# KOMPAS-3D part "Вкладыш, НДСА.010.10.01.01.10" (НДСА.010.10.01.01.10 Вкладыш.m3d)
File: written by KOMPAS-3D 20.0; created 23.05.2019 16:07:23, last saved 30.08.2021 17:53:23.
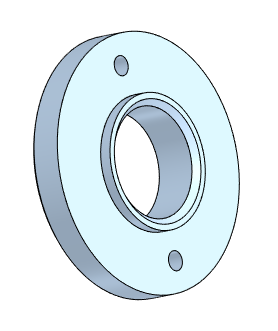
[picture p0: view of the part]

Document properties: Автор: Пользователь Windows; Полное имя файла: C:\Users\korychko\Desktop\PLM\НДСА.010.10.01.01.10 Вкладыш.m3d

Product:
- Part/product: Вкладыш  | designation НДСА.010.10.01.01.10
    Масса: 0.0537653
    additional columns: <item xmlns="http://appius.ru/pdm" xmlns:xs="http://www.w3.org/2001/XMLSchema" x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; <item xmlns="http://appius.ru/pdm" xmlns:xs="http://www.w3.org/2001/XMLSchema" x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; <item xmlns="http://appius.ru/pdm" xmlns:xs="http://www.w3.org/2001/XMLSchema" x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; <item xmlns="http://appius.ru/pdm" xmlns:xs="http://www.w3.org/2001/XMLSchema" x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; <item xmlns="http://appius.ru/pdm" xmlns:xs="http://www.w3.org/2001/XMLSchema" x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; <item xmlns="http://appius.ru/pdm" xmlns:xs="http://www.w3.org/2001/XMLSchema" x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; <item xmlns="http://appius.ru/pdm" xmlns:xs="http://www.w3.org/2001/XMLSchema" x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; <item xmlns="http://appius.ru/pdm" xmlns:xs="http://www.w3.org/2001/XMLSchema" x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
    source file: НДСА.010.10.01.01.10 Вкладыш.cdw

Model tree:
1. Эскиз:1
2. Элемент выдавливания:1
     Расстояние 1 = 8
3. Эскиз:2  (with: Элемент выдавливания:1)
4. Элемент выдавливания:2
     Расстояние 2 = 2
5. Фаска:1  (with: Элемент выдавливания:1)
     Угол = 45; Длина 1 = 1; Длина 2 = 1
6. Эскиз:3  (with: Элемент выдавливания:1, Фаска:1)
7. Элемент выдавливания:3
     Расстояние 2 = 10
8. Условное изображение резьбы:1  (with: Элемент выдавливания:3)  (labels: cil0_24705-2004 coarse; M4)
     Длина резьбы = 6; Шаг резьбы = 0.7; Номинальный диаметр резьбы = 4
9. Подгонка:1  (with: Элемент выдавливания:3)
10. Условное изображение резьбы:2  (with: Элемент выдавливания:3)  (labels: cil0_24705-2004 coarse; M4)
     Длина резьбы = 6; Шаг резьбы = 0.7; Номинальный диаметр резьбы = 4
11. Подгонка:2  (with: Элемент выдавливания:3)

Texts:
  НДСА.010.10.01.01.10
